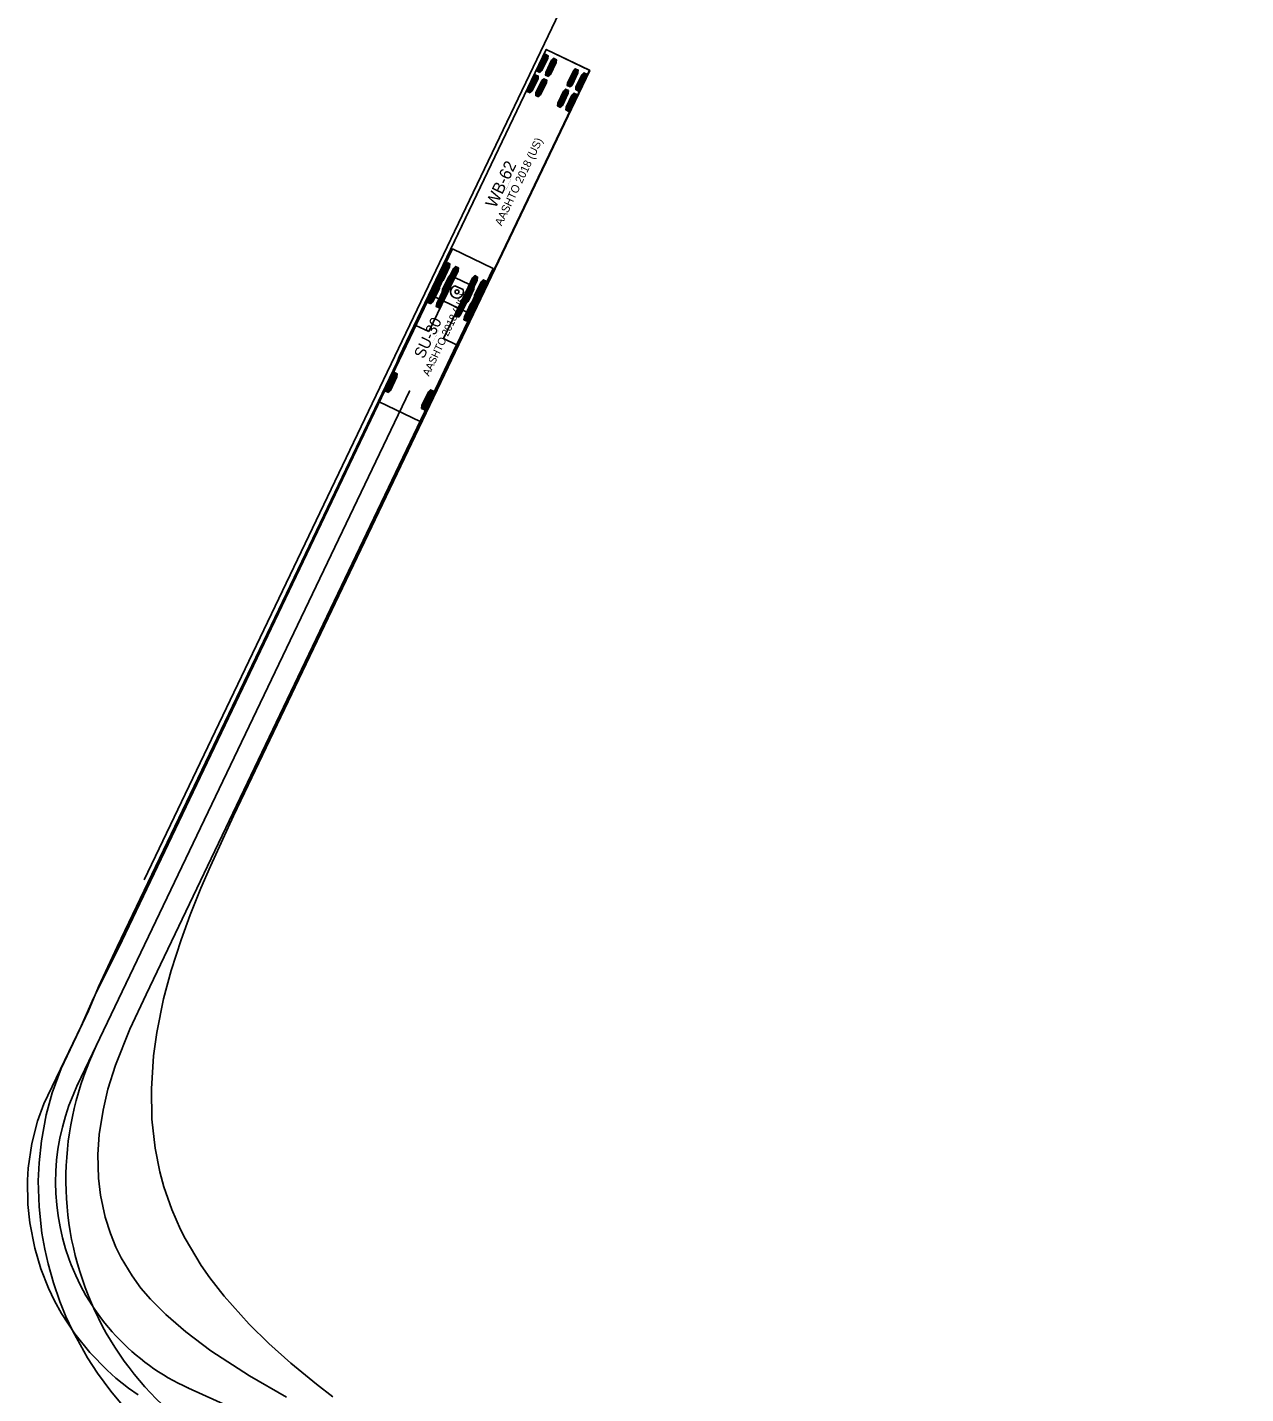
# Model space of a CAD drawing. Extents: x 186128 to 186702, y 352195 to 353183.
# Drawn here: x 186220.4 to 186436, y 352438.5 to 352680.4 of the extents above; entities that cross this region are included whole.
import ezdxf

# ---------------------------------------------------------------- set-up
doc = ezdxf.new("R2010")
doc.units = 0
doc.layers.add('SV_X_Control_Cells_Found', color=7, linetype='Continuous')
doc.layers.add('SV_X_Shot_Marker', color=7, linetype='Continuous')

msp = doc.modelspace()

# ---------------------------------------------------------------- linework, layer by layer
at = {"layer": 'SV_X_Control_Cells_Found'}
for p, q in [((186295.63, 352641.16), (186282.69, 352614.1)), ((186302.85, 352637.71), (186295.63, 352641.16)), ((186289.9, 352610.64), (186302.85, 352637.71)), ((186292.51, 352634.15), (186293.95, 352637.16)), ((186292.7, 352634.06), (186294.14, 352637.07)), ((186292.89, 352633.97), (186294.32, 352636.98)), ((186293.86, 352633.51), (186295.3, 352636.51)), ((186294.05, 352633.42), (186295.49, 352636.42)), ((186294.24, 352633.33), (186295.68, 352636.33)), ((186297.62, 352631.71), (186299.06, 352634.72)), ((186297.81, 352631.62), (186299.25, 352634.63)), ((186298, 352631.53), (186299.44, 352634.54)), ((186298.97, 352631.06), (186300.41, 352634.07)), ((186299.16, 352630.97), (186300.6, 352633.98)), ((186299.35, 352630.88), (186300.79, 352633.89)), ((186283.88, 352616.11), (186285.32, 352619.12)), ((186284.07, 352616.02), (186285.51, 352619.03)), ((186284.26, 352615.93), (186285.69, 352618.94)), ((186229.31, 352493.23), (186288.02, 352615.98)), ((186282.69, 352614.1), (186289.9, 352610.64)), ((186290.35, 352613.02), (186291.78, 352616.03)), ((186290.53, 352612.93), (186291.97, 352615.94)), ((186290.72, 352612.84), (186292.16, 352615.85)), ((186289.9, 352610.64), (186289.9, 352610.64)), ((186248.92, 352439.53), (186435.98, 352354.92))]:
    msp.add_line(p, q, dxfattribs=at)
for points in [[(186240.03, 352438.31), (186238.32, 352439.53), (186236.09, 352441.3), (186234.52, 352442.71), (186231.47, 352445.83), (186228.84, 352449.11), (186226.48, 352452.71), (186225.23, 352454.98), (186224.15, 352457.24), (186222.81, 352460.65), (186221.72, 352464.3), (186220.84, 352468.76), (186220.48, 352472.04), (186220.41, 352476.34), (186220.54, 352478.44), (186221.2, 352482.83), (186222.21, 352486.77), (186223.33, 352489.82), (186229.92, 352503.6), (186232.12, 352508.55), (186236.52, 352517.41), (186295.61, 352641.17), (186302.82, 352637.69), (186241.41, 352509.18), (186238.55, 352503.04), (186236.03, 352496.71), (186234.68, 352492.41), (186233.8, 352488.71), (186233.14, 352484.44), (186232.91, 352480.86), (186233.01, 352476.66), (186233.37, 352473.68), (186234.19, 352469.78), (186235.11, 352466.89), (186236.09, 352464.46), (186237.01, 352462.56), (186238.95, 352459.37), (186240.52, 352457.21), (186242.19, 352455.27), (186244.89, 352452.58), (186248.43, 352449.5), (186252.89, 352446.15), (186259.71, 352441.69), (186266.24, 352437.92)], [(186292.93, 352633.95), (186292.46, 352634.18), (186292.52, 352634.66), (186293.56, 352636.83), (186293.9, 352637.18), (186294.37, 352636.96), (186294.31, 352636.47), (186293.27, 352634.3), (186292.93, 352633.95)], [(186294.28, 352633.3), (186293.82, 352633.53), (186293.88, 352634.02), (186294.91, 352636.18), (186295.25, 352636.54), (186295.72, 352636.31), (186295.66, 352635.82), (186294.63, 352633.66), (186294.28, 352633.3)], [(186298.04, 352631.51), (186297.57, 352631.73), (186297.63, 352632.22), (186298.67, 352634.38), (186299.01, 352634.74), (186299.48, 352634.51), (186299.42, 352634.02), (186298.39, 352631.86), (186298.04, 352631.51)], [(186299.4, 352630.86), (186298.93, 352631.08), (186298.99, 352631.57), (186300.02, 352633.74), (186300.37, 352634.09), (186300.84, 352633.87), (186300.78, 352633.38), (186299.74, 352631.21), (186299.4, 352630.86)], [(186284.3, 352615.91), (186283.83, 352616.13), (186283.89, 352616.62), (186284.93, 352618.79), (186285.27, 352619.14), (186285.74, 352618.92), (186285.68, 352618.43), (186284.65, 352616.26), (186284.3, 352615.91)], [(186290.77, 352612.82), (186290.3, 352613.04), (186290.36, 352613.53), (186291.39, 352615.69), (186291.74, 352616.05), (186292.21, 352615.82), (186292.15, 352615.33), (186291.11, 352613.17), (186290.77, 352612.82)]]:
    msp.add_lwpolyline(points, dxfattribs=at)
for centre in [(186288.02, 352615.98), (186229.31, 352493.23), (186229.31, 352493.23), (186248.92, 352439.53), (186248.92, 352439.53)]:
    msp.add_circle(centre, 0.0417, dxfattribs=at)
msp.add_arc((186265.4, 352475.98), 40, 154.4396, 245.6635, dxfattribs=at)
at = {"layer": 'SV_X_Shot_Marker'}
for p, q in [((186241.11, 352529.49), (186330.07, 352715.49)), ((186312.23, 352676.45), (186291.52, 352633.15)), ((186310.65, 352672.61), (186312.07, 352675.58)), ((186310.85, 352672.51), (186312.28, 352675.49)), ((186311.06, 352672.41), (186312.48, 352675.39)), ((186312.14, 352671.9), (186313.56, 352674.87)), ((186319.9, 352672.78), (186312.23, 352676.45)), ((186312.34, 352671.8), (186313.77, 352674.77)), ((186312.55, 352671.7), (186313.97, 352674.67)), ((186299.19, 352629.48), (186319.9, 352672.78)), ((186316, 352670.05), (186317.42, 352673.02)), ((186316.21, 352669.95), (186317.63, 352672.93)), ((186316.41, 352669.85), (186317.84, 352672.83)), ((186317.49, 352669.34), (186318.91, 352672.31)), ((186317.69, 352669.24), (186319.12, 352672.21)), ((186308.92, 352669), (186310.34, 352671.98)), ((186309.13, 352668.9), (186310.55, 352671.88)), ((186309.33, 352668.8), (186310.76, 352671.78)), ((186310.41, 352668.29), (186311.83, 352671.26)), ((186310.62, 352668.19), (186312.04, 352671.17)), ((186310.82, 352668.09), (186312.25, 352671.07)), ((186317.9, 352669.14), (186319.33, 352672.11)), ((186314.27, 352666.44), (186315.7, 352669.42)), ((186314.48, 352666.34), (186315.9, 352669.32)), ((186314.69, 352666.24), (186316.11, 352669.22)), ((186315.76, 352665.73), (186317.19, 352668.7)), ((186315.97, 352665.63), (186317.39, 352668.61)), ((186316.18, 352665.53), (186317.6, 352668.51)), ((186293.15, 352635.44), (186294.73, 352638.74)), ((186293.35, 352635.34), (186294.94, 352638.65)), ((186293.56, 352635.24), (186295.14, 352638.55)), ((186296.05, 352636.08), (186291.47, 352626.52)), ((186294.63, 352634.73), (186296.22, 352638.03)), ((186294.84, 352634.63), (186296.42, 352637.93)), ((186295.05, 352634.53), (186296.63, 352637.84)), ((186298.63, 352634.85), (186296.05, 352636.08)), ((186298.05, 352633.09), (186299.63, 352636.4)), ((186298.25, 352632.99), (186299.84, 352636.3)), ((186298.46, 352632.9), (186300.04, 352636.2)), ((186291.33, 352631.65), (186292.92, 352634.96)), ((186291.54, 352631.55), (186293.12, 352634.86)), ((186291.75, 352631.45), (186293.33, 352634.76)), ((186292.82, 352630.94), (186294.4, 352634.24)), ((186293.03, 352630.84), (186294.61, 352634.15)), ((186293.24, 352630.74), (186294.82, 352634.05)), ((186294.06, 352625.28), (186298.63, 352634.85)), ((186297.51, 352633.95), (186296.05, 352634.65)), ((186299.54, 352632.38), (186301.12, 352635.69)), ((186299.74, 352632.28), (186301.33, 352635.59)), ((186299.95, 352632.18), (186301.53, 352635.49)), ((186291.52, 352633.15), (186299.19, 352629.48)), ((186296.24, 352629.3), (186297.82, 352632.61)), ((186296.44, 352629.2), (186298.02, 352632.51)), ((186296.65, 352629.11), (186298.23, 352632.41)), ((186297.72, 352628.59), (186299.31, 352631.9)), ((186297.93, 352628.49), (186299.51, 352631.8)), ((186298.14, 352628.39), (186299.72, 352631.7)), ((186299.19, 352629.48), (186299.19, 352629.48)), ((186289.16, 352627.63), (186282.69, 352614.1)), ((186291.47, 352626.52), (186289.16, 352627.63)), ((186289.9, 352610.64), (186296.37, 352624.18)), ((186296.37, 352624.18), (186294.06, 352625.28)), ((186283.83, 352615.95), (186285.41, 352619.26)), ((186284.03, 352615.85), (186285.62, 352619.16)), ((186284.24, 352615.75), (186285.82, 352619.06)), ((186232.61, 352500.12), (186288.02, 352615.98)), ((186282.69, 352614.1), (186289.9, 352610.64)), ((186290.22, 352612.89), (186291.8, 352616.2)), ((186290.42, 352612.8), (186292.01, 352616.1)), ((186290.63, 352612.7), (186292.21, 352616)), ((186289.9, 352610.64), (186289.9, 352610.64))]:
    msp.add_line(p, q, dxfattribs=at)
for points in [[(186237.17, 352436.57), (186235.17, 352438.97), (186232.81, 352442.18), (186231.04, 352444.9), (186228.45, 352449.6), (186227.23, 352452.22), (186226.15, 352454.88), (186225.03, 352458.16), (186224.08, 352461.54), (186223.49, 352464.13), (186223, 352466.95), (186222.48, 352471.61), (186222.34, 352476.2), (186222.48, 352479.39), (186222.9, 352483.29), (186223.75, 352487.88), (186224.8, 352491.79), (186226.38, 352496.12), (186231.23, 352506.29), (186233.01, 352510.55), (186236.32, 352517.64), (186269, 352585.85), (186285.8, 352621.02), (186286.19, 352622.04), (186312.24, 352676.47), (186319.92, 352672.76), (186256.86, 352540.84), (186252.79, 352531.91), (186251.12, 352528.01), (186249.25, 352523.32), (186247.61, 352518.85), (186245.87, 352513.44), (186244.52, 352508.42), (186243.31, 352502.48), (186242.75, 352498.32), (186242.36, 352492.48), (186242.46, 352487.1), (186243.01, 352482.01), (186243.83, 352477.78), (186244.56, 352475.15), (186245.97, 352471.12), (186247.51, 352467.61), (186248.33, 352466), (186251.18, 352461.24), (186252.72, 352459.04), (186255.25, 352455.8), (186259.65, 352450.87), (186263.16, 352447.43), (186267.03, 352443.95), (186271.56, 352440.21), (186274.44, 352437.98)], [(186311.11, 352672.39), (186310.6, 352672.63), (186310.64, 352673.12), (186311.66, 352675.27), (186312.02, 352675.61), (186312.54, 352675.36), (186312.49, 352674.87), (186311.47, 352672.73), (186311.11, 352672.39)], [(186312.6, 352671.67), (186312.08, 352671.92), (186312.13, 352672.41), (186313.15, 352674.55), (186313.51, 352674.9), (186314.02, 352674.65), (186313.98, 352674.16), (186312.95, 352672.02), (186312.6, 352671.67)], [(186316.46, 352669.83), (186315.95, 352670.07), (186315.99, 352670.56), (186317.02, 352672.71), (186317.37, 352673.05), (186317.89, 352672.8), (186317.84, 352672.31), (186316.82, 352670.17), (186316.46, 352669.83)], [(186317.95, 352669.11), (186317.44, 352669.36), (186317.48, 352669.85), (186318.51, 352671.99), (186318.86, 352672.34), (186319.38, 352672.09), (186319.33, 352671.6), (186318.31, 352669.46), (186317.95, 352669.11)], [(186309.39, 352668.78), (186308.87, 352669.02), (186308.91, 352669.51), (186309.94, 352671.66), (186310.29, 352672), (186310.81, 352671.75), (186310.77, 352671.26), (186309.74, 352669.12), (186309.39, 352668.78)], [(186310.87, 352668.06), (186310.36, 352668.31), (186310.4, 352668.8), (186311.43, 352670.95), (186311.78, 352671.29), (186312.3, 352671.04), (186312.25, 352670.55), (186311.23, 352668.41), (186310.87, 352668.06)], [(186314.74, 352666.22), (186314.22, 352666.46), (186314.27, 352666.95), (186315.29, 352669.1), (186315.65, 352669.44), (186316.16, 352669.19), (186316.12, 352668.7), (186315.09, 352666.56), (186314.74, 352666.22)], [(186316.23, 352665.5), (186315.71, 352665.75), (186315.75, 352666.24), (186316.78, 352668.39), (186317.13, 352668.73), (186317.65, 352668.48), (186317.61, 352667.99), (186316.58, 352665.85), (186316.23, 352665.5)], [(186293.61, 352635.21), (186293.1, 352635.46), (186293.16, 352636), (186294.3, 352638.38), (186294.68, 352638.77), (186295.19, 352638.52), (186295.13, 352637.99), (186293.99, 352635.6), (186293.61, 352635.21)], [(186295.1, 352634.5), (186294.58, 352634.75), (186294.65, 352635.29), (186295.79, 352637.67), (186296.17, 352638.06), (186296.68, 352637.81), (186296.62, 352637.27), (186295.48, 352634.89), (186295.1, 352634.5)], [(186298.51, 352632.87), (186298, 352633.12), (186298.06, 352633.65), (186299.2, 352636.04), (186299.58, 352636.43), (186300.09, 352636.18), (186300.03, 352635.64), (186298.89, 352633.26), (186298.51, 352632.87)], [(186291.8, 352631.43), (186291.28, 352631.67), (186291.35, 352632.21), (186292.49, 352634.59), (186292.87, 352634.98), (186293.38, 352634.73), (186293.32, 352634.2), (186292.18, 352631.81), (186291.8, 352631.43)], [(186293.29, 352630.71), (186292.77, 352630.96), (186292.84, 352631.5), (186293.98, 352633.88), (186294.35, 352634.27), (186294.87, 352634.02), (186294.8, 352633.48), (186293.66, 352631.1), (186293.29, 352630.71)], [(186300, 352632.16), (186299.49, 352632.41), (186299.55, 352632.94), (186300.69, 352635.32), (186301.07, 352635.71), (186301.58, 352635.47), (186301.52, 352634.93), (186300.38, 352632.55), (186300, 352632.16)], [(186296.7, 352629.08), (186296.18, 352629.33), (186296.25, 352629.87), (186297.39, 352632.25), (186297.77, 352632.64), (186298.28, 352632.39), (186298.22, 352631.85), (186297.08, 352629.47), (186296.7, 352629.08)], [(186298.19, 352628.37), (186297.67, 352628.62), (186297.74, 352629.15), (186298.88, 352631.54), (186299.26, 352631.92), (186299.77, 352631.68), (186299.71, 352631.14), (186298.57, 352628.76), (186298.19, 352628.37)], [(186284.29, 352615.73), (186283.78, 352615.98), (186283.84, 352616.51), (186284.98, 352618.89), (186285.36, 352619.28), (186285.87, 352619.04), (186285.81, 352618.5), (186284.67, 352616.12), (186284.29, 352615.73)], [(186290.68, 352612.67), (186290.17, 352612.92), (186290.23, 352613.46), (186291.37, 352615.84), (186291.75, 352616.23), (186292.26, 352615.98), (186292.2, 352615.44), (186291.06, 352613.06), (186290.68, 352612.67)]]:
    msp.add_lwpolyline(points, dxfattribs=at)
for centre, radius in [((186296.43, 352633.57), 0.34), ((186288.02, 352615.98), 0.0417), ((186232.61, 352500.12), 0.0417), ((186232.61, 352500.12), 0.0417)]:
    msp.add_circle(centre, radius, dxfattribs=at)
for centre, radius, start, end in [((186296.43, 352633.57), 1.14, 109.4396, 19.4396), ((186282.23, 352476.39), 55, 154.4396, 252.2963)]:
    msp.add_arc(centre, radius, start, end, dxfattribs=at)

# ---------------------------------------------------------------- texts
at = {"layer": 'SV_X_Control_Cells_Found'}
for s, height, p in [('AASHTO 2018 (US)', 1.3333, (186291.46, 352618.53)), ('SU-30', 2, (186290.53, 352621.59)), ('(c) 2025 Transoft Solutions, Inc. All rights reserved.', 0.08, (186292.1, 352624.41))]:
    msp.add_text(s, height=height, rotation=64.4396, dxfattribs=at).set_placement(p)
at = {"layer": 'SV_X_Shot_Marker'}
for s, height, p in [('AASHTO 2018 (US)', 1.4167, (186304.33, 352645.13)), ('WB-62', 2.125, (186303.26, 352648.25)), ('(c) 2025 Transoft Solutions, Inc. All rights reserved.', 0.085, (186305, 352651.38))]:
    msp.add_text(s, height=height, rotation=64.4396, dxfattribs=at).set_placement(p)

doc.saveas('drawing.dxf')
